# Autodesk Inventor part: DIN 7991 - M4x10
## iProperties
Created: 2007-03
Part Number: DIN 7991 - M4x10
Material: Steel, Mild
Description: Hexagon socket countersunk head cap screws
Document SubType Name: Modeling
Standard: DIN 7991
Designer: Andy Moles
Standards Organization: DIN
Language: en-US
Size Designation: M4x8
Categories: <MemberInstance Version="R10.0.0"><Categories><Category DisplayName="Fasteners" InternalName="e4da775c-781d-43d5-af7c-5136215cf5a6" Mnemonic="FSTN"><Category Di
Density: 7.86 g/cm^3
Author: Andy Moles
Revision Number: 1
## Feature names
1. Revolution1
2. Extrusion1
3. Fillet1
4. Chamfer1
